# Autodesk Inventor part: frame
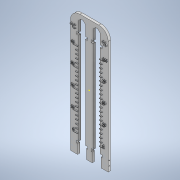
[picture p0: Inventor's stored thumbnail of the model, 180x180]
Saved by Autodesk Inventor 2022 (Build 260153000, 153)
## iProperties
Created: 2022-12
Part Number: frame
Material: Generic
Document SubType Name: Modeling
Designer: suerfu
Density: 1 g/cm^3
Appearance: Default
Author: suerfu
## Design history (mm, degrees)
sketch "Sketch1" dims "d23" = 25.4
  geometry: L1 (-25.4, 82.55)-(25.4, 82.55); L2 (25.4, 82.55)-(25.4, -82.55); L3 (25.4, -82.55)-(-25.4, -82.55); L4 (-25.4, -82.55)-(-25.4, 82.55); L5 (-11.405, 77.47)-(-8.255, 77.47); L6 (-5.08, 74.295)-(-5.08, -82.55); L7 (-5.08, -82.55)-(-14.58, -82.55); L8 (-14.58, -82.55)-(-14.58, 74.295); L9 (8.255, 77.47)-(11.405, 77.47); L10 (14.58, 74.295)-(14.58, -82.55); L11 (14.58, -82.55)-(5.08, -82.55); L12 (5.08, -82.55)-(5.08, 74.295); L13 (-25.4, -80.01)-(-25.4, -69.85); L14 (25.4, -80.01)-(25.4, -69.85); L15 (-14.58, -69.85)-(-17.12, -69.85); L16 (-17.12, -69.85)-(-17.12, -66.675); L17 (-17.12, -66.675)-(-14.58, -66.675); L18 (-14.58, -66.675)-(-14.58, -69.85); L19 (-5.08, -66.675)-(-2.54, -66.675); L20 (-2.54, -66.675)-(-2.54, -69.85); L21 (-2.54, -69.85)-(-5.08, -69.85); L22 (-5.08, -69.85)-(-5.08, -66.675); L23 (5.08, -66.675)-(2.54, -66.675); L24 (2.54, -66.675)-(2.54, -69.85); L25 (2.54, -69.85)-(5.08, -69.85); L26 (5.08, -69.85)-(5.08, -66.675); L27 (14.58, -66.675)-(17.12, -66.675); L28 (17.12, -66.675)-(17.12, -69.85); L29 (17.12, -69.85)-(14.58, -69.85); L30 (14.58, -69.85)-(14.58, -66.675); L31 (-17.12, 57.15)-(-17.12, 60.325); L32 (-17.12, 60.325)-(-14.58, 60.325); L33 (-14.58, 57.15)-(-17.12, 57.15); L34 (-5.08, 60.325)-(-2.54, 60.325); L35 (-2.54, 60.325)-(-2.54, 57.15); L36 (-2.54, 57.15)-(-5.08, 57.15); L37 (5.08, 60.325)-(2.54, 60.325); L38 (2.54, 60.325)-(2.54, 57.15); L39 (2.54, 57.15)-(5.08, 57.15); L40 (14.58, 60.325)-(17.12, 60.325); L41 (17.12, 60.325)-(17.12, 57.15); L42 (17.12, 57.15)-(14.58, 57.15); L43 (-11.405, 77.47)-(-14.58, 74.295); L44 (-8.255, 77.47)-(-5.08, 74.295); L45 (5.08, 74.295)-(8.255, 77.47); L46 (11.405, 77.47)-(14.58, 74.295); L47 (-15.85, -69.85)-(-15.85, -82.55); L48 (-3.81, -69.85)-(-3.81, -82.55); L49 (3.81, -69.85)-(3.81, -82.55); L50 (15.85, -69.85)-(15.85, -82.55); 21 further points
  constraints: 100 end point, 30 point on line, 14 parallel, 10 perpendicular, 7 horizontal, 4 equal length, 4 midpoint, 2 vertical, 1 collinear, 28 other
  dimensions: "d0" = 165.1 distance of L3.end L1.start; "d1" = 50.8 distance of L1.start L1.end; "d2" = 82.55 distance from line of L1 point (0, 0) (= 0.5 x d0); "d3" = 25.4 distance from line of point (0, 0) L4 (= 0.5 x d1); "d4" = 9.5 distance of point (-14.58, 77.47) point (-5.08, 77.47); "d5" = 9.5 distance of point (5.08, 77.47) point (14.58, 77.47); "d6" = 5.08 distance from line of L12 point (0, 0); "d7" = 5.08 distance from line of point (0, 0) L6 (= d6); "d8" = 10.82 distance between parallel lines of L2 L10 (derived); "d9" = 160.02 distance of L7.end point (-14.58, 77.47); "d10" = 10.82 distance between parallel lines of L8 L4 (derived); "d16" = 2.54 distance of L16.end L17.end; "d17" = 3.175 distance of L15.end L16.end; "d20" = 127 distance of L15.end L31.start; "d25" = 20.32 distance between parallel lines of L5 L33 (derived); "d26" = 3.175 distance of L5.start point (-14.58, 77.47) (derived); "d27" = 3.175 distance of L8.end point (-14.58, 77.47) (= d26); "d28" = 3.175 distance of L5.end point (-5.08, 77.47) (= d26); "d29" = 3.175 distance of L6.start point (-5.08, 77.47) (= d28); "d30" = 3.175 distance of L12.end point (5.08, 77.47) (= d26); "d31" = 3.175 distance of L9.start point (5.08, 77.47) (= d30); "d32" = 3.175 distance of L9.end point (14.58, 77.47) (= d26); "d33" = 3.175 distance of L10.start point (14.58, 77.47) (= d32); "d35" = 12.7 distance between parallel lines of L3 L15
extrude "Extrusion1" new body sketch "Sketch1" distance "d14" = 3.175; taper "d15" = 0 deg
sketch "Sketch2"
  geometry: 1 further point
fillet "Fillet1" dims "d37" = 12.7
sketch "Sketch4"
  geometry: L1 (0, 147.32)-(0, -5.08) reference; L2 (0, 0)-(3.175, 0) reference; L3 (0, -5.08)-(3.175, -5.08) reference; C1 r 0.508 at (1.587, 1.27); C2 r 0.508 at (1.587, 7.62); 1 further point
  constraints: 2 centre point, 1 vertical alignment
  dimensions: "d39" = 1.016 diameter of C1; "d40" = 1.016 diameter of C2 (= d39); "d41" = 1.5875 distance from line of L1 C1.centre; "d43" = 6.35 distance of C1.centre C2.centre; "d49" = 6.35 distance from line of L3 C1.centre
extrude "Extrusion2" cut sketch "Sketch4" distance "d44" = 6.35; taper "d45" = 0 deg
sketch "Sketch5"
  geometry: L1 (0, -5.08)-(-3.175, -5.08) reference; C1 r 0.508 at (-1.587, 7.62); C2 r 0.508 at (-1.587, 1.27); C3 r 0.508 at (-1.587, 7.62) reference; C4 r 0.508 at (-1.587, 1.27) reference; 2 further points
  constraints: 2 centre point, 2 concentric, 2 equal radius
extrude "Extrusion3" cut sketch "Sketch5" distance "d46" = 6.35; taper "d47" = 0 deg
sketch "Sketch6"
  geometry: L1 (-21.147, -53.341)-(-19.66, -53.341); L2 (-19.66, -53.341)-(-19.66, -56.515); L3 (-19.66, -56.515)-(-21.147, -56.515); L4 (-21.147, -56.515)-(-21.147, -53.341); L5 (-20.85, -27.941)-(-19.66, -27.941); L6 (-19.66, -27.941)-(-19.66, -31.115); L7 (-19.66, -31.115)-(-20.85, -31.115); L8 (-20.85, -31.115)-(-20.85, -27.941); L9 (-21.271, -2.539)-(-19.66, -2.539); L10 (-19.66, -2.539)-(-19.66, -5.715); L11 (-19.66, -5.715)-(-21.271, -5.715); L12 (-21.271, -5.715)-(-21.271, -2.539); L13 (-21.587, 22.861)-(-19.66, 22.861); L14 (-19.66, 22.861)-(-19.66, 19.685); L15 (-19.66, 19.685)-(-21.587, 19.685); L16 (-21.587, 19.685)-(-21.587, 22.861); L17 (-20.429, 48.259)-(-19.66, 48.259); L18 (-19.66, 48.259)-(-19.66, 45.085); L19 (-19.66, 45.085)-(-20.429, 45.085); L20 (-20.429, 45.085)-(-20.429, 48.259); L21 (18.39, -53.976)-(21.32, -53.976); L22 (21.32, -53.976)-(21.32, -56.515); L23 (21.32, -56.515)-(18.39, -56.515); L24 (18.39, -56.515)-(18.39, -53.976); L25 (18.39, -28.574)-(25.081, -28.574); L26 (25.081, -28.574)-(25.081, -31.115); L27 (25.081, -31.115)-(18.39, -31.115); L28 (18.39, -31.115)-(18.39, -28.574); L29 (18.39, -3.176)-(23.608, -3.176); L30 (23.608, -3.176)-(23.608, -5.715); L31 (23.608, -5.715)-(18.39, -5.715); L32 (18.39, -5.715)-(18.39, -3.176); L33 (18.39, 22.162)-(23.187, 22.162); L34 (23.187, 22.162)-(23.187, 19.685); L35 (23.187, 19.685)-(18.39, 19.685); L36 (18.39, 19.685)-(18.39, 22.162); L37 (18.39, 47.624)-(25.158, 47.624); L38 (25.158, 47.624)-(25.158, 45.085); L39 (25.158, 45.085)-(18.39, 45.085); L40 (18.39, 45.085)-(18.39, 47.624); L41 (-22.313, 66.022)-(-17.755, 66.022); L42 (-17.755, 66.022)-(-17.755, 62.865); L43 (-17.755, 62.865)-(-22.313, 62.865); L44 (-22.313, 62.865)-(-22.313, 66.022); L45 (17.755, 68.413)-(24.653, 68.413); L46 (24.653, 68.413)-(24.653, 62.865); L47 (24.653, 62.865)-(17.755, 62.865); L48 (17.755, 62.865)-(17.755, 68.413); L49 (-17.12, -66.675)-(-14.58, -66.675) reference; L50 (14.58, 57.15)-(14.58, -66.675) reference; L51 (-14.58, -66.675)-(-14.58, 57.15) reference; L52 (-14.58, 57.15)-(-17.12, 57.15); L53 (17.12, 57.15)-(14.58, 57.15); L54 (-14.58, 60.325)-(-14.58, 74.295) reference; L55 (14.58, 74.295)-(14.58, 60.325) reference; L56 (-17.12, 60.325)-(-14.58, 60.325) reference; 1 further point
  constraints: 14 collinear, 4 end point, 24 other
  dimensions: "d52" = 10.16 distance between parallel lines of L3 L49; "d53" = 25.4 distance between parallel lines of L3 L7; "d54" = 25.4 distance between parallel lines of L11 L7 (= d53); "d55" = 25.4 distance between parallel lines of L11 L15 (= d53); "d56" = 25.4 distance between parallel lines of L15 L19 (= d53); "d57" = 3.81 distance between parallel lines of L40 L50; "d58" = 5.08 distance between parallel lines of L51 L18; "d92" = 3.175 distance between parallel lines of L54 L42; "d93" = 3.175 distance between parallel lines of L55 L48 (derived); "d94" = 2.54 distance between parallel lines of L56 L43
extrude "Extrusion4" join sketch "Sketch6" distance "d59" = 1.27; taper "d60" = 0 deg
sketch "Sketch7" dims "d69" = 25.4, "d77" = 25.4
  geometry: L1 (-20.93, -56.833)-(-14.58, -56.833); L2 (-14.58, -56.833)-(-14.58, -57.468); L3 (-14.58, -57.468)-(-20.93, -57.468); L4 (-20.93, -57.468)-(-20.93, -56.833); L5 (-17.12, -66.675)-(-14.58, -66.675) reference; L6 (-20.93, -32.068)-(-20.93, -31.433); L7 (-20.93, -31.433)-(-14.58, -31.433); L8 (-14.58, -32.068)-(-20.93, -32.068); L9 (-14.58, -31.433)-(-14.58, -32.068); L10 (-20.93, -6.668)-(-20.93, -6.033); L11 (-20.93, -6.033)-(-14.58, -6.033); L12 (-14.58, -6.668)-(-20.93, -6.668); L13 (-14.58, -6.033)-(-14.58, -6.668); L14 (-20.93, 18.732)-(-20.93, 19.367); L15 (-20.93, 19.367)-(-14.58, 19.367); L16 (-14.58, 18.732)-(-20.93, 18.732); L17 (-14.58, 19.367)-(-14.58, 18.732); L18 (-20.93, 44.132)-(-20.93, 44.767); L19 (-20.93, 44.767)-(-14.58, 44.767); L20 (-14.58, 44.132)-(-20.93, 44.132); L21 (-14.58, 44.767)-(-14.58, 44.132); L22 (20.93, -57.468)-(14.58, -57.468); L23 (14.58, -57.468)-(14.58, -56.833); L24 (14.58, -56.833)-(20.93, -56.833); L25 (20.93, -56.833)-(20.93, -57.468); L26 (14.58, -31.433)-(20.93, -31.433); L27 (20.93, -32.068)-(14.58, -32.068); L28 (20.93, -31.433)-(20.93, -32.068); L29 (14.58, -32.068)-(14.58, -31.433); L30 (14.58, -6.033)-(20.93, -6.033); L31 (20.93, -6.668)-(14.58, -6.668); L32 (20.93, -6.033)-(20.93, -6.668); L33 (14.58, -6.668)-(14.58, -6.033); L34 (14.58, 19.367)-(20.93, 19.367); L35 (20.93, 18.732)-(14.58, 18.732); L36 (20.93, 19.367)-(20.93, 18.732); L37 (14.58, 18.732)-(14.58, 19.367); L38 (14.58, 44.767)-(20.93, 44.767); L39 (20.93, 44.132)-(14.58, 44.132); L40 (20.93, 44.767)-(20.93, 44.132); L41 (14.58, 44.132)-(14.58, 44.767); L42 (-17.755, -52.388)-(-14.58, -52.388); L43 (-14.58, -52.388)-(-14.58, -51.752); L44 (-14.58, -51.752)-(-17.755, -51.752); L45 (-17.755, -51.752)-(-17.755, -52.388); L46 (-17.755, -46.672)-(-17.755, -47.308); L47 (-14.58, -46.672)-(-17.755, -46.672); L48 (-17.755, -47.308)-(-14.58, -47.308); L49 (-14.58, -47.308)-(-14.58, -46.672); L50 (-17.755, -41.593)-(-17.755, -42.228); L51 (-14.58, -41.593)-(-17.755, -41.593); L52 (-17.755, -42.228)-(-14.58, -42.228); L53 (-14.58, -42.228)-(-14.58, -41.593); L54 (-17.755, -36.513)-(-17.755, -37.148); L55 (-14.58, -36.513)-(-17.755, -36.513); L56 (-17.755, -37.148)-(-14.58, -37.148); L57 (-14.58, -37.148)-(-14.58, -36.513); L58 (-17.755, -31.433)-(-17.755, -32.068); L59 (-14.58, -31.433)-(-17.755, -31.433); L60 (-17.755, -32.068)-(-14.58, -32.068); L61 (-14.58, -32.068)-(-14.58, -31.433); L62 (-17.755, -26.352)-(-17.755, -26.988); L63 (-14.58, -26.352)-(-17.755, -26.352); L64 (-17.755, -26.988)-(-14.58, -26.988)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; 85 further points
  constraints: 400 end point, 108 vertical alignment, 60 parallel, 55 collinear, 4 horizontal, 3 perpendicular, 2 equal length, 2 vertical, 163 other
  dimensions: "d61" = 0.635 distance of L3.end L1.start; "d62" = 6.35 distance of L2.end L3.end; "d63" = 9.2075 distance between parallel lines of L5 L3 (computed from d61); "d66" = 25.4 distance of L3.end L6.start; "d71" = 35.51 dimension on L10 (derived); "d74" = 25.4 distance of L23.end L26.start; "d79" = 3.175 distance of L42.start L42.end (= 0.5 x d62); "d80" = 4.445 distance between parallel lines of L1 L42 (computed from d61, d81); "d81" = 0.635 distance of L44.end L42.start; "d84" = 5.08 distance of L44.end L46.start; "d87" = 32.335 distance of L44.end L122.start (= d71 - d79)
extrude "Extrusion5" join sketch "Sketch7" distance "d90" = 1.27; taper "d91" = 0 deg
body "Solid1"
other parameters: "d38" = 5.08
